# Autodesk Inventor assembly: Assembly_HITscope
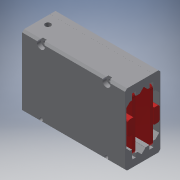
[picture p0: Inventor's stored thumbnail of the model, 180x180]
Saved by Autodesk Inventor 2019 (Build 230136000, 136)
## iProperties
Created: 2021-09
Part Number: Assembly_HITscope
Material: Generisch
Document SubType Name: Assembly
Designer: Muriel
Author: Muriel
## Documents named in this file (2)
- C:\Users\Muriel\Documents\Inventor\HITscope\Assembly_HITscope.iam
- C:\Users\Muriel\Documents\Inventor\HITscope\HITscope_v0.iam
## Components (2 placed, 1 different names)
1. HITscope_v0:1 [sub-assembly] — Passend:1, Fluchtend:1, Winkel:1, Fluchtend:2, Fluchtend:3
2. HITscope_v0:3 [sub-assembly] — Passend:1, Fluchtend:1, Winkel:1, Fluchtend:2, Fluchtend:3
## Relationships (5: Flush 3, Mate 1, Angle 1)
- Passend:1 [Mate]: HITscope_v0:1 ↔ HITscope_v0:3
- Fluchtend:1 [Flush]: HITscope_v0:1 ↔ HITscope_v0:3
- Winkel:1 [Angle]: HITscope_v0:1 ↔ HITscope_v0:3
- Fluchtend:2 [Flush]: HITscope_v0:1 ↔ HITscope_v0:3
- Fluchtend:3 [Flush]: HITscope_v0:1 ↔ HITscope_v0:3
